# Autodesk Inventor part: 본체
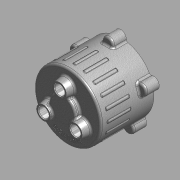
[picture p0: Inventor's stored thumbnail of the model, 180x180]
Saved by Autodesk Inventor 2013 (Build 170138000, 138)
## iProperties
Created: 2015-11
Part Number: 본체
Document SubType Name: 모델링
Designer: mdu
Material: 일반
Density: 1 g/cm^3
변환 표준: STEP AP214IS
파일 이름: C:\Users\SeoGD\Desktop\?쒗뿕\紐몄껜.stp
전처리기: Build: 253, Release: 2010 SP1 - Date: Wed 07/29/2009
전송 단위: 밀리미터
불확실성: 0.01
Author: mdu
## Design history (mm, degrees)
sketch "스케치2"
  geometry: C1 r 50 at (0, 0); 1 further point
  constraints: 1 centre point, 1 coincident
  dimensions: "d9" = 100 diameter of C1
extrude "돌출2" new body sketch "스케치2" distance "d10" = 80; taper "d11" = 0 deg
feature "쉘1" dims "d12" = 5
sketch "스케치3" dims "d13" = 55
  geometry: C1 r 7.5 at (0, 27.5); C2 r 12.5 at (0, 27.5); 2 further points
  constraints: 2 centre point, 2 coincident, 2 vertical alignment, 2 other
  dimensions: "d14" = 15 diameter of C1; "d15" = 25 diameter of C2
extrude "돌출3" join sketch "스케치3" distance "d16" = 12; taper "d17" = -10 deg
hole "구멍2" diameter "d20" = 15; stored, may be unused: countersink angle "d24" = 90 deg, drill point angle "d26" = 118 deg; dims "d18" = 10, "d19" = 10, "d21" = 6, "d22" = 4, "d23" = 2, "d25" = 15
chamfer "모따기1" distance "d27" = 1; stored, may be unused: second distance "d28" = 2, angle "d29" = 45 deg
sketch "스케치4"
  geometry: L1 (0, 0)-(0, 88); L2 (0, 70)-(13.16, 70); L3 (-45, 75)-(45, 75) reference; L4 (-50, 80)-(50, 80) reference; L5 (13.16, 70)-(14.5, 75); L6 (20, 80)-(20, 88); L7 (20, 88)-(0, 88); L8 (20, 80)-(14.5, 75)
  constraints: 12 end point, 3 point on line, 2 perpendicular, 1 vertical
  dimensions: "d34" = 40 diameter of L6 L1; "d35" = 105 deg angle of L5 L3; "d36" = 5 distance between parallel lines of L2 L3; "d37" = 8 distance between parallel lines of L7 L4; "d51" = 29 diameter of L5.end L1
revolve "회전1" sketch "스케치4" stored, may be unused: angle "d38" = 90 deg
hole "구멍3" diameter "d41" = 15; stored, may be unused: countersink angle "d45" = 90 deg, drill point angle "d47" = 0 deg; dims "d39" = 10, "d40" = 10, "d42" = 6, "d43" = 22, "d44" = 13, "d46" = 15
chamfer "모따기2" distance "d48" = 1; stored, may be unused: second distance "d49" = 2, angle "d50" = 45 deg
fillet "모깎기1" dims "d52" = 3
fillet "모깎기2" dims "d53" = 3, "d72" = 0.2
sketch "스케치5"
  geometry: A1 r 50 centre (0, 0) between (50, 0) and (-8.074, 49.344) reference; A2 r 8.5 centre (0, 52) between (8.074, 49.344) and (-8.074, 49.344); 1 further point
  constraints: 5 point on circle, 1 centre point, 1 horizontal alignment
  dimensions: "d54" = 90 deg dimension on point (0, 0) A2.centre A1.start; "d55" = 52 distance of A2.centre point (0, 0); "d56" = 17 diameter of A2
extrude "돌출4" join sketch "스케치5" distance "d57" = 20; taper "d58" = 0 deg
fillet "모깎기3" dims "d59" = 3
hole "구멍4" diameter "d62" = 4.134; stored, may be unused: countersink angle "d66" = 90 deg, drill point angle "d68" = 118 deg; dims "d60" = 10, "d61" = 10, "d63" = 12, "d64" = 22, "d65" = 13, "d67" = 15
sketch "스케치6"
  geometry: C1 r 47 at (0, 0) reference; C2 r 42.5 at (0, 0); 1 further point
  constraints: 1 centre point, 1 coincident, 1 other
  dimensions: "d73" = 85 diameter of C2
feature "엠보싱1" sketch "스케치6" dims "d74" = 0.5, "d75" = 0
node "작업 평면1"
sketch "스케치7"
  geometry: A1 r 50 centre (0, 0) between (5.144, 49.735) and (-5.144, 49.735) reference; A2 r 3 centre (0, 47.916) between (2.204, 49.951) and (-2.204, 49.951); 1 further point
  constraints: 4 point on circle, 1 centre point, 1 vertical alignment
  dimensions: "d77" = 3 radius of A2
extrude "돌출5" join sketch "스케치7" distance "d79" = 35; taper "d80" = 0 deg
fillet "모깎기4" dims "d81" = 1
fillet "모깎기5" dims "d82" = 1
node "솔리드1"
node "솔리드 본체"
node "곡면 본체"
pattern_circular "원형 패턴1" dims "d31" = 360 deg
pattern_circular "원형 패턴2" dims "d70" = 360 deg
pattern_circular "원형 패턴3" dims "d84" = 360 deg
node "솔리드2"
